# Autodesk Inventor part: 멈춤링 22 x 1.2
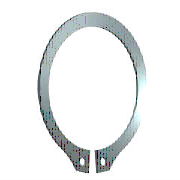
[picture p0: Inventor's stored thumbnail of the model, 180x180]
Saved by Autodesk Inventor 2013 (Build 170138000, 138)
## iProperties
IsCustomPart: 0
Company: 한국ATC센터
Created: 2009-02
Part Number: 멈춤링 22 x 1.2
Material: Steel, Mild
Description: 리테이닝 링(C형)
Document SubType Name: Modeling
Standard: KS B 1336
Designer: KYOUNG IL JANG
Standards Organization: KS
Language: ko-KR
Size Designation: 22 x 1.2
Categories: <MemberInstance><Categories><Category DisplayName="샤프트 부품" InternalName="7f7aeb1f-a693-4053-b835-cee3144e0d98" Mnemonic="SHFT"><Category DisplayName="써클립" Inter
Density: 7.86 g/cm^3
Mass: 1.8286 g
Surface Area: 5.91219 cm^2
Volume: 0.232646 cm^3
Author: KYOUNG IL JANG
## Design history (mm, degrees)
sketch "스케치1"
  geometry: L1 (-6, 0)-(6, 0) reference; L2 (0, 20.189)-(0, -80.536) reference; L3 (-48.09, 0)-(48.09, 0) reference; L4 (-0.5, -21.488)-(-0.5, -25.588); L5 (-0.5, -6.54)-(-0.5, -13.29); L6 (-2.795, 2.7)-(3.672, 2.7); L7 (0.5, -6.54)-(0.5, -13.29); L8 (0.5, -21.488)-(0.5, -25.588); C1 r 1 at (-2, -23.437); C2 r 1 at (2, -23.437); A1 r 10.5 centre (0, -11) between (0.5, -21.488) and (-0.5, -21.488); A2 r 13.025 centre (0, -10.325) between (5.149, -22.289) and (-5.149, -22.289); A3 r 14.597 centre (0, -11) between (-2.318, -25.411) and (-0.5, -25.588); A4 r 2 centre (-2, -23.437) between (-3.97, -23.781) and (-2.318, -25.411); A5 r 2 centre (-5.94, -24.126) between (-3.97, -23.781) and (-5.149, -22.289); A6 r 2 centre (5.94, -24.126) between (5.149, -22.289) and (3.97, -23.781); A7 r 2 centre (2, -23.437) between (2.318, -25.411) and (3.97, -23.781); A8 r 14.597 centre (0, -11) between (0.5, -25.588) and (2.318, -25.411)
  constraints: 16 point on circle, 12 end point, 10 centre point, 9 symmetric about line, 5 point on line, 4 tangent, 3 coincident, 2 horizontal, 1 perpendicular, 1 vertical, 5 other
  dimensions: "d0" = 21 diameter of A1 (= ND); "d1" = 4.1 distance of L4.end L4.start (= SRB2); "d6" = 0.5 distance between parallel lines of L2 L5 (= 0.25 x SD5); "d7" = 2.7 distance between parallel lines of L6 L3 (= SRB1); "d8" = 0.675 distance of A1.centre A2.centre (= 0.25 x SRB1); "d9" = 2 radius of A4 (= SD5); "d10" = 2 radius of A5 (= SD5); "d11" = 1.5 distance from line of L4 A4.centre (= 0.75 x SD5); "d12" = 2 diameter of C1 (= SD5); "d13" = 2 diameter of C2 (= SD5); "d14" = 11 distance from line of A1.centre L1 (= 0.5 x WD)
extrude "본체" new body sketch "스케치1" distance "d2" = 1.2 (= SD); taper "d3" = 0 deg
workaxis "Work Axis1"
workplane "Work Plane1"
body "Solid1"
other parameters: "WD" = 22 (= WDMIN) [user parameter; used in 1 equation term], "SD" = 1.2 [user parameter; used in 1 equation term], "SRB1" = 2.7 [user parameter; used in 2 equation terms], "ND" = 21 [user parameter; used in 1 equation term], "SRB2" = 4.1 [user parameter; used in 1 equation term], "SD5" = 2 [user parameter; used in 6 equation terms], "d15" = 0, "d16" = 0, "d17" = 0, "d41" = 0, "d42" = 0, "WDMIN" = 22 [user parameter; used in 1 equation term], "SD3" = 20.5 [user parameter], "WDMAX" = 24 [user parameter]
